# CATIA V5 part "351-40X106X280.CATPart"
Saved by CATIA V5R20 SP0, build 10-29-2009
Part number: 351-40X106X280
Definition: NONE
Nomenclature: 351-40X106X280
Source: Unknown
Description: 351-40X106X280
Bounding box of the stored display mesh (mm): x -8 to 272, y -26 to 26, z -26 to 26
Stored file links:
  C:\Users\Utente\Desktop\IO LAVORO\3D X SITO CF\X SITO\PLASTICA\351\351-40X106X280.CATPart

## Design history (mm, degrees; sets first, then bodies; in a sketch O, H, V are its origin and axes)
Body1 "351-40X106X280" (main body)
  Solid1: solid without history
